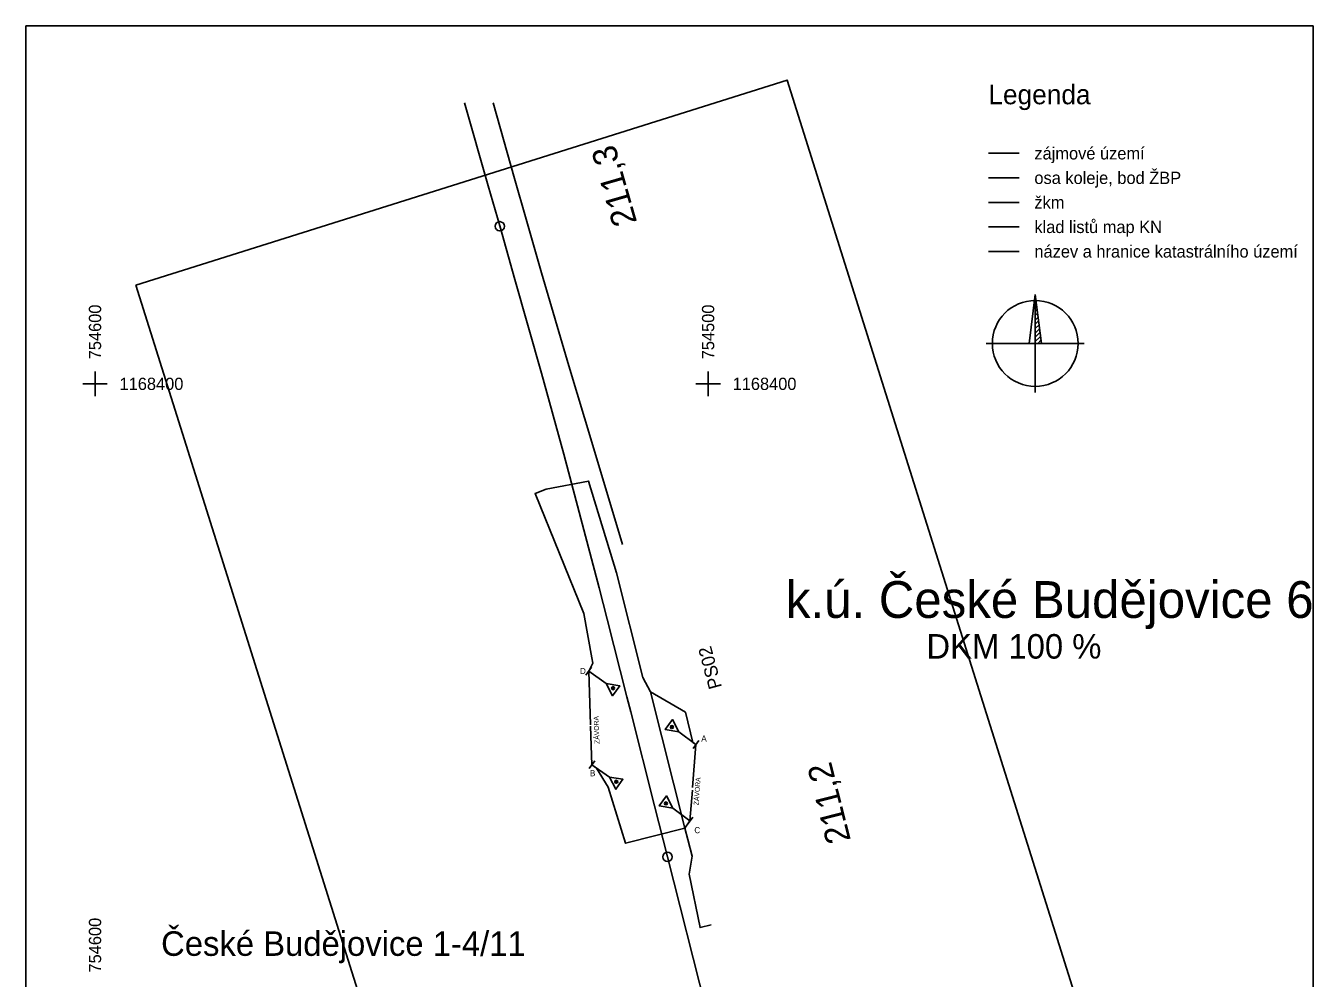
# Model space of a CAD drawing. Extents: x -754611 to -754273, y -1169136 to -1168342.
# Drawn here: x -754611.3 to -754401.3, y -1168496.9 to -1168341.6 of the extents above; entities that cross this region are included whole.
import ezdxf

# ---------------------------------------------------------------- set-up
doc = ezdxf.new("R2010")
doc.units = 0
for name, color, linetype in [('Vrstva 1', 7, 'Continuous'), ('Vrstva 13', 7, 'Continuous'), ('Vrstva 23', 7, 'Continuous'), ('Vrstva 24', 7, 'Continuous'), ('Vrstva 3', 7, 'Continuous'), ('Vrstva 4', 7, 'Continuous'), ('Vrstva 45', 7, 'Continuous'), ('Vrstva 61', 7, 'Continuous'), ('Vrstva 62', 7, 'Continuous'), ('Vrstva 63', 7, 'Continuous'), ('Vrstva 7', 7, 'Continuous')]:
    doc.layers.add(name, color=color, linetype=linetype)

msp = doc.modelspace()

# ---------------------------------------------------------------- linework, layer by layer
at = {"layer": 'Vrstva 1'}
for p, q in [((-754535.88, -1168367.71), (-754539.75, -1168354.18)), ((-754454.28, -1168366.41), (-754449.28, -1168366.41))]:
    msp.add_line(p, q, dxfattribs=at)
for points in [[(-754487.87, -1168551.32), (-754489.69, -1168544.13), (-754495.86, -1168519.7), (-754500.17, -1168502.64), (-754500.22, -1168502.46), (-754500.39, -1168501.79), (-754506.63, -1168477.15), (-754508.73, -1168468.84), (-754512.62, -1168453.46), (-754513.24, -1168451.02), (-754516.47, -1168438.36), (-754517.79, -1168433.24), (-754523.55, -1168411.48), (-754527.19, -1168398.27), (-754531.51, -1168382.98), (-754533.99, -1168374.26), (-754535.88, -1168367.71), (-754539.75, -1168354.18)], [(-754513.99, -1168426.21), (-754518.82, -1168410.04), (-754522.69, -1168397.05), (-754527.17, -1168381.88), (-754529.7, -1168373.15), (-754531.6, -1168366.53), (-754535.08, -1168354.18)], [(-754519.17, -1168455.59), (-754519.47, -1168446.86)], [(-754518.94, -1168462.12), (-754519.16, -1168455.85)], [(-754502.54, -1168465.84), (-754501.99, -1168458.81)], [(-754502.96, -1168471.26), (-754502.57, -1168466.27)]]:
    msp.add_lwpolyline(points, dxfattribs=at)
for centre in [(-754533.98, -1168374.3), (-754506.63, -1168477.14)]:
    msp.add_circle(centre, 0.75, dxfattribs=at)
at = {"layer": 'Vrstva 13'}
msp.add_line((-754454.28, -1168378.41), (-754449.28, -1168378.41), dxfattribs=at)
at = {"layer": 'Vrstva 23'}
msp.add_line((-754454.28, -1168362.41), (-754449.28, -1168362.41), dxfattribs=at)
msp.add_lwpolyline([(-754593.32, -1168383.89), (-754540.15, -1168552.9), (-754433.92, -1168519.48), (-754487.09, -1168350.47)], close=True, dxfattribs=at)
at = {"layer": 'Vrstva 3'}
msp.add_line((-754454.28, -1168374.41), (-754449.28, -1168374.41), dxfattribs=at)
for points in [[(-754600, -1168402), (-754600, -1168400), (-754600, -1168398)], [(-754500, -1168402), (-754500, -1168400), (-754500, -1168398)], [(-754602, -1168400), (-754600, -1168400), (-754598, -1168400)], [(-754502, -1168400), (-754500, -1168400), (-754498, -1168400)]]:
    msp.add_lwpolyline(points, dxfattribs=at)
at = {"layer": 'Vrstva 4'}
for p, q in [((-754519.02, -1168446.23), (-754519.92, -1168447.5)), ((-754515.54, -1168449.39), (-754515.46, -1168449.88)), ((-754505.88, -1168456.22), (-754505.95, -1168455.73)), ((-754502.45, -1168459.44), (-754501.53, -1168458.18)), ((-754518.49, -1168461.48), (-754519.39, -1168462.75)), ((-754515.01, -1168464.65), (-754514.93, -1168465.13)), ((-754506.85, -1168468.67), (-754506.92, -1168468.19)), ((-754503.42, -1168471.89), (-754502.5, -1168470.64))]:
    msp.add_line(p, q, dxfattribs=at)
for points in [[(-754519.47, -1168446.86), (-754516.63, -1168448.87), (-754514.42, -1168449.22), (-754515.57, -1168450.86), (-754516.63, -1168448.87)], [(-754501.99, -1168458.81), (-754504.79, -1168456.76), (-754507, -1168456.37), (-754505.82, -1168454.75), (-754504.79, -1168456.76)], [(-754518.94, -1168462.12), (-754516.1, -1168464.12), (-754513.9, -1168464.48), (-754515.05, -1168466.11), (-754516.1, -1168464.12)], [(-754502.96, -1168471.26), (-754505.77, -1168469.21), (-754507.97, -1168468.82), (-754506.79, -1168467.2), (-754505.77, -1168469.21)]]:
    msp.add_lwpolyline(points, dxfattribs=at)
for centre in [(-754515.5, -1168449.63), (-754505.91, -1168455.97), (-754514.97, -1168464.89), (-754506.89, -1168468.43)]:
    msp.add_circle(centre, 0.248, dxfattribs=at)
at = {"layer": 'Vrstva 45'}
msp.add_line((-754503.77, -1168472.48), (-754502.96, -1168471.26), dxfattribs=at)
for points in [[(-754519.47, -1168446.86), (-754518.79, -1168445.56), (-754518.97, -1168444.66), (-754520.27, -1168437.46), (-754528.21, -1168417.88), (-754526.42, -1168417.16), (-754519.52, -1168415.85), (-754514.96, -1168430.83), (-754510.67, -1168447.87), (-754509.4, -1168450.23)], [(-754503.77, -1168472.48), (-754509.4, -1168450.23)], [(-754509.4, -1168450.23), (-754503.68, -1168453.56), (-754502.47, -1168458.49), (-754501.99, -1168458.81)], [(-754518.94, -1168462.12), (-754518.19, -1168462.65), (-754516.3, -1168465.76), (-754513.47, -1168474.91), (-754503.77, -1168472.48)], [(-754503.77, -1168472.48), (-754503.3, -1168474.33)], [(-754503.3, -1168474.33), (-754502.62, -1168477.03), (-754503.11, -1168479.94), (-754501.32, -1168488.67), (-754499.51, -1168488.21)]]:
    msp.add_lwpolyline(points, dxfattribs=at)
at = {"layer": 'Vrstva 61'}
msp.add_line((-754401.3, -1168341.61), (-754611.3, -1168341.61), dxfattribs=at)
msp.add_lwpolyline([(-754611.3, -1168341.61), (-754611.3, -1168638.61), (-754401.3, -1168638.61), (-754401.3, -1168341.61)], dxfattribs=at)
at = {"layer": 'Vrstva 62'}
for p, q in [((-754446.64, -1168385.41), (-754446.64, -1168401.41)), ((-754446.64, -1168386.05), (-754446.57, -1168385.98)), ((-754446.64, -1168386.76), (-754446.5, -1168386.61)), ((-754446.64, -1168387.46), (-754446.42, -1168387.24)), ((-754446.64, -1168388.17), (-754446.34, -1168387.87)), ((-754446.64, -1168388.88), (-754446.26, -1168388.49)), ((-754446.64, -1168389.59), (-754446.18, -1168389.12)), ((-754446.64, -1168390.29), (-754446.1, -1168389.75)), ((-754446.64, -1168391), (-754446.02, -1168390.38)), ((-754446.64, -1168391.71), (-754445.95, -1168391.01)), ((-754446.64, -1168392.41), (-754445.87, -1168391.64)), ((-754454.64, -1168393.41), (-754438.64, -1168393.41)), ((-754446.64, -1168393.12), (-754445.79, -1168392.27)), ((-754446.23, -1168393.41), (-754445.71, -1168392.89))]:
    msp.add_line(p, q, dxfattribs=at)
for points in [[(-754446.64, -1168385.41), (-754447.64, -1168393.41)], [(-754446.64, -1168385.41), (-754446.64, -1168393.41), (-754445.64, -1168393.41), (-754446.64, -1168385.41)]]:
    msp.add_lwpolyline(points, dxfattribs=at)
msp.add_circle((-754446.64, -1168393.41), 7, dxfattribs=at)
at = {"layer": 'Vrstva 7'}
msp.add_line((-754454.28, -1168370.41), (-754449.28, -1168370.41), dxfattribs=at)

# ---------------------------------------------------------------- texts
at = {"layer": 'Vrstva 13'}
msp.add_text('název a hranice katastrálního území', height=2, dxfattribs=at).set_placement((-754446.78, -1168379.41))
at = {"layer": 'Vrstva 23'}
msp.add_text('zájmové území', height=2, dxfattribs=at).set_placement((-754446.78, -1168363.41))
at = {"layer": 'Vrstva 24'}
for s, height, p in [('k.ú. České Budějovice 6', 6, (-754487.32, -1168438.17)), ('DKM 100 %', 4, (-754464.39, -1168444.81))]:
    msp.add_text(s, height=height, dxfattribs=at).set_placement(p)
at = {"layer": 'Vrstva 3'}
for s, height, p in [('klad listů map KN', 2, (-754446.78, -1168375.41)), ('1168400', 2, (-754596, -1168401)), ('1168400', 2, (-754496, -1168401)), ('České Budějovice 1-4/11', 4, (-754589.22, -1168493.28))]:
    msp.add_text(s, height=height, dxfattribs=at).set_placement(p)
for s, height, rotation, p in [('754600', 2, 90, (-754599, -1168396)), ('754500', 2, 90, (-754499, -1168396)), ('PS02', 2.16, 105, (-754497.72, -1168449.44)), ('754600', 2, 90, (-754599, -1168496))]:
    msp.add_text(s, height=height, rotation=rotation, dxfattribs=at).set_placement(p)
at = {"layer": 'Vrstva 4'}
for s, p in [('D', (-754520.91, -1168447.32)), ('A', (-754501.12, -1168458.33)), ('B', (-754519.28, -1168463.99)), ('C', (-754502.25, -1168473.28))]:
    msp.add_text(s, height=1, dxfattribs=at).set_placement(p)
for rotation, p in [(92.0732, (-754517.71, -1168458.7)), (85.5249, (-754501.56, -1168468.73))]:
    msp.add_text('ZÁVORA', height=0.8, rotation=rotation, dxfattribs=at).set_placement(p)
at = {"layer": 'Vrstva 62'}
msp.add_text('Legenda', height=3.2, dxfattribs=at).set_placement((-754454.28, -1168354.41))
at = {"layer": 'Vrstva 63'}
msp.add_text('osa koleje, bod ŽBP', height=2, dxfattribs=at).set_placement((-754446.78, -1168367.41))
at = {"layer": 'Vrstva 7'}
for s, rotation, p in [('211,3', 106.0493, (-754511.56, -1168373.64)), ('211,2', 104.1901, (-754476.7, -1168474.41))]:
    msp.add_text(s, height=4, rotation=rotation, dxfattribs=at).set_placement(p)
msp.add_text('žkm', height=2, dxfattribs=at).set_placement((-754446.78, -1168371.41))

doc.saveas('drawing.dxf')
